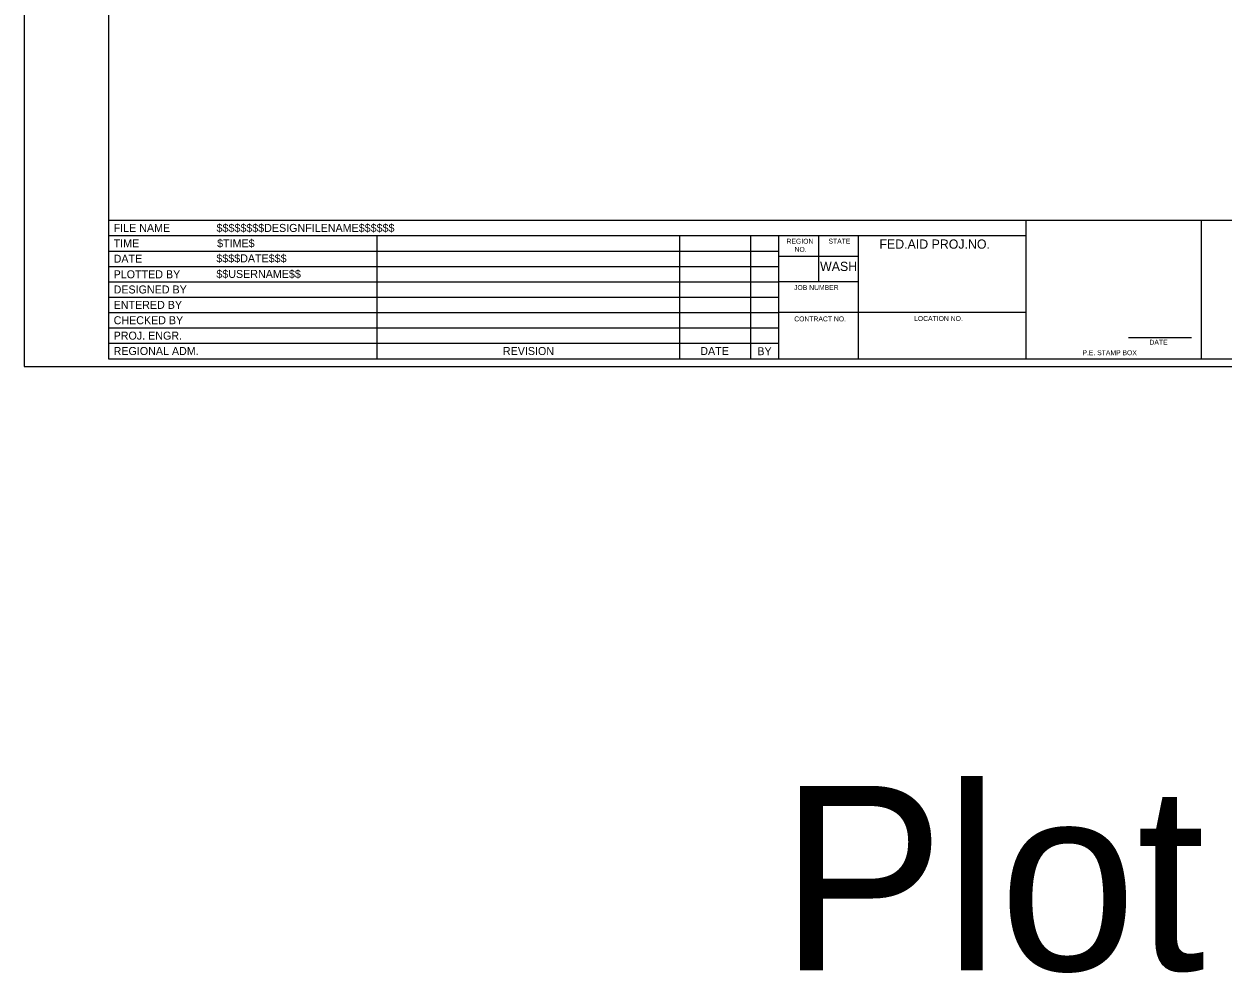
# Model space of a CAD drawing. Extents: x 99988 to 100172, y 99995 to 100047.
# Drawn here: x 99999.31 to 100009.07, y 99995.01 to 100002.72 of the extents above; entities that cross this region are included whole.
import ezdxf

# ---------------------------------------------------------------- set-up
doc = ezdxf.new("R2010")
doc.units = 0
for name, color, linetype in [('SH_GI_PlotLimits', 7, 'Continuous'), ('SH_GI_SheetBorder', 7, 'Continuous'), ('SH_GI_SheetLocationText', 7, 'Continuous'), ('SH_GI_SheetTextInCells', 7, 'Continuous'), ('SH_GI_TitleBlockText', 7, 'Continuous')]:
    doc.layers.add(name, color=color, linetype=linetype)

msp = doc.modelspace()

# ---------------------------------------------------------------- linework, layer by layer
at = {"layer": 'SH_GI_PlotLimits'}
msp.add_lwpolyline([(99999.3125, 99999.9375), (100015.8125, 99999.9375), (100015.8125, 100010.4375), (99999.3125, 100010.4375)], close=True, dxfattribs=at)
at = {"layer": 'SH_GI_SheetBorder'}
for p, q in [((100000, 100010.375), (100000, 100000)), ((100000, 100001.1259), (100015.75, 100001.1259)), ((100007.4566, 100000), (100007.4566, 100001.1259)), ((100008.8828, 100000), (100008.8828, 100001.1259)), ((100000, 100001.0008), (100007.4566, 100001.0008)), ((100002.179, 100001.0008), (100002.179, 100000)), ((100004.641, 100001.0008), (100004.641, 100000)), ((100005.2164, 100001.0008), (100005.2164, 100000)), ((100005.4451, 100001.0008), (100005.4451, 100000)), ((100005.7719, 100000.6255), (100005.7719, 100001.0008)), ((100006.0956, 100000), (100006.0956, 100001.0008)), ((100000, 100000.8757), (100002.1821, 100000.8757)), ((100002.1821, 100000.8757), (100005.4466, 100000.8757)), ((100006.0958, 100000.831), (100005.4466, 100000.831)), ((100000, 100000.7506), (100002.1821, 100000.7506)), ((100002.1821, 100000.7506), (100005.4466, 100000.7506)), ((100000, 100000.6255), (100005.4466, 100000.6255)), ((100006.0958, 100000.6255), (100005.4466, 100000.6255)), ((100000, 100000.5004), (100005.4466, 100000.5004)), ((100000, 100000.3753), (100005.4466, 100000.3753)), ((100007.4566, 100000.3753), (100005.4466, 100000.3753)), ((100000, 100000.2502), (100005.4466, 100000.2502)), ((100008.2903, 100000.1733), (100008.802, 100000.1733)), ((100000, 100000.1251), (100005.4466, 100000.1251)), ((100000, 100000), (100015.75, 100000))]:
    msp.add_line(p, q, dxfattribs=at)

# ---------------------------------------------------------------- texts
at = {"layer": 'SH_GI_SheetLocationText'}
msp.add_text('Plot 1', height=1.5, dxfattribs=at).set_placement((100005.4547, 99995.0267))
at = {"layer": 'SH_GI_SheetTextInCells'}
for s, height, p in [('FILE NAME', 0.06505, (100000.041, 100001.0308)), ('TIME', 0.06505, (100000.041, 100000.9057)), ('REGION', 0.04003, (100005.5099, 100000.9352)), ('NO.', 0.04003, (100005.5752, 100000.869)), ('STATE', 0.04003, (100005.8511, 100000.9357)), ('FED.AID PROJ.NO.', 0.07506, (100006.2652, 100000.8945)), ('DATE', 0.06505, (100000.041, 100000.7806)), ('PLOTTED BY', 0.06505, (100000.041, 100000.6538)), ('WASH', 0.07506, (100005.7826, 100000.7131)), ('DESIGNED BY', 0.065052, (100000.041, 100000.5304)), ('JOB NUMBER', 0.04003, (100005.5712, 100000.5587)), ('ENTERED BY', 0.06505, (100000.041, 100000.4053)), ('CHECKED BY', 0.06505, (100000.041, 100000.2802)), ('CONTRACT NO.', 0.040032, (100005.5725, 100000.3037)), ('LOCATION NO.', 0.040032, (100006.5465, 100000.3067)), ('PROJ. ENGR.', 0.065052, (100000.041, 100000.1551)), ('DATE', 0.04003, (100008.4597, 100000.1141)), ('REGIONAL ADM.', 0.065052, (100000.041, 100000.03)), ('REVISION', 0.06505, (100003.2048, 100000.03)), ('DATE', 0.06505, (100004.8091, 100000.03)), ('BY', 0.06505, (100005.2725, 100000.0285)), ('P.E. STAMP BOX', 0.040032, (100007.915, 100000.0286))]:
    msp.add_text(s, height=height, dxfattribs=at).set_placement(p)
at = {"layer": 'SH_GI_TitleBlockText'}
for s, height, p in [('$$$$$$$$DESIGNFILENAME$$$$$$', 0.065052, (100000.8775, 100001.0308)), ('$TIME$', 0.06505, (100000.882, 100000.9059)), ('$$$$DATE$$$', 0.065052, (100000.8759, 100000.7835)), ('$$USERNAME$$', 0.065052, (100000.8759, 100000.6567))]:
    msp.add_text(s, height=height, dxfattribs=at).set_placement(p)

doc.saveas('drawing.dxf')
